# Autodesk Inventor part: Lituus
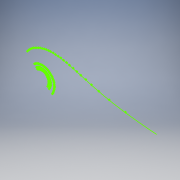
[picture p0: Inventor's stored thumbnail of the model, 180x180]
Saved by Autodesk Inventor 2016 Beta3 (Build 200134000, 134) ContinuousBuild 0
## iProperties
Created: 2008-02
Part Number: Lituus
Document SubType Name: Modeling
Designer: Autodesk, Inc.
Density: 1 g/cm^3
Material: Generic
Appearance: Default
Author: Autodesk, Inc.
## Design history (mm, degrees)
sketch "Sketch1"
  geometry: 300 further points
  constraints: 300 other
